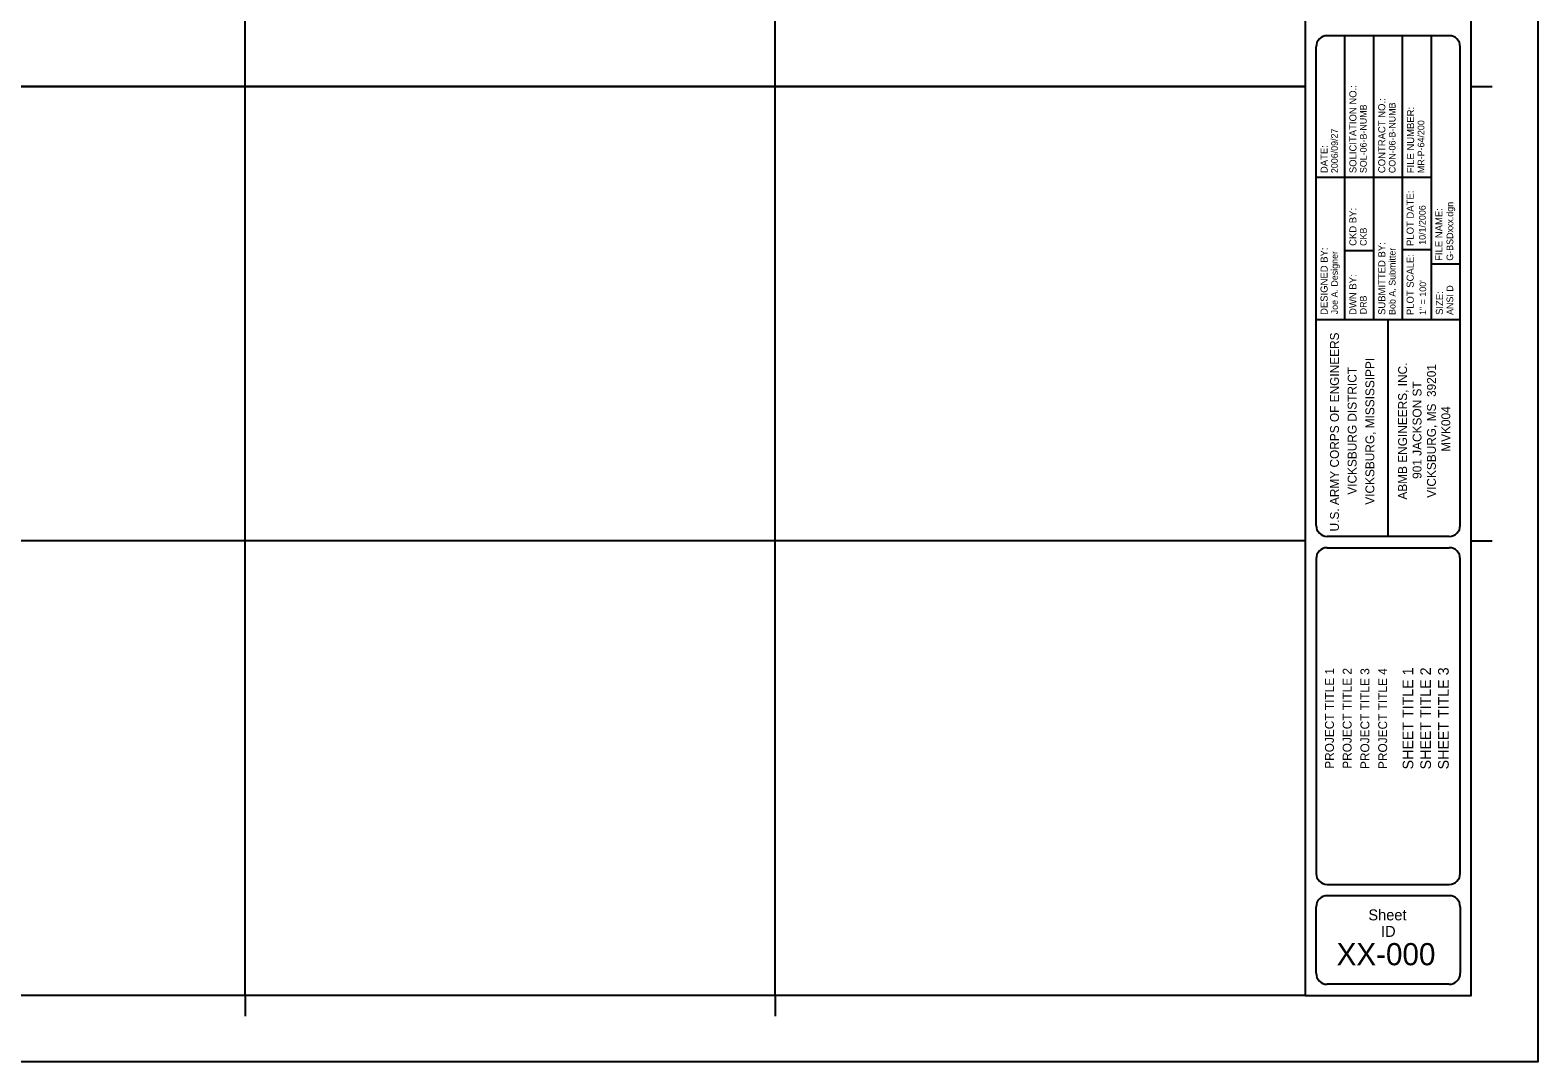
# Model space of a CAD drawing. Extents: x 0 to 2.83, y 0 to 1.83.
# Drawn here: x 1.417 to 2.833, y 0 to 0.97 of the extents above; entities that cross this region are included whole.
import ezdxf

# ---------------------------------------------------------------- set-up
doc = ezdxf.new("R2010")
doc.units = 0
for name, color, linetype in [('G-ANNO-NPLT', 7, 'Continuous'), ('G-ANNO-PRFL', 7, 'Continuous'), ('G-ANNO-TEXT', 7, 'Continuous'), ('G-ANNO-TEXT-SAMP', 7, 'Continuous'), ('G-ANNO-TTLB', 7, 'Continuous'), ('G-ANNO-TTLB-GRID', 7, 'Continuous')]:
    doc.layers.add(name, color=color, linetype=linetype)

msp = doc.modelspace()

# ---------------------------------------------------------------- linework, layer by layer
at = {"layer": 'G-ANNO-NPLT'}
msp.add_line((2.7708, 0.0625), (2.7708, 0.0625), dxfattribs=at)
msp.add_line((2.7708, 0.0625), (2.7708, 0.0625), dxfattribs=at)
msp.add_line((2.7708, 0.0625), (2.7708, 0.0625), dxfattribs=at)
msp.add_line((2.7708, 0.0625), (2.7708, 0.0625), dxfattribs=at)
at = {"layer": 'G-ANNO-PRFL'}
msp.add_line((0.125, 0.9167), (2.6146, 0.9167), dxfattribs=at)
at = {"layer": 'G-ANNO-TEXT'}
for p, q in [((2.7708, 0.9167), (2.7905, 0.9167)), ((2.7708, 0.4896), (2.7905, 0.4896))]:
    msp.add_line(p, q, dxfattribs=at)
at = {"layer": 'G-ANNO-TTLB'}
for p, q in [((2.6521, 0.6979), (2.6521, 0.9646)), ((2.6792, 0.6979), (2.6792, 0.9646)), ((2.7063, 0.6979), (2.7063, 0.9646)), ((2.7333, 0.6979), (2.7333, 0.9646)), ((2.625, 0.5042), (2.625, 0.9542)), ((2.6522, 0.8313), (2.625, 0.8313)), ((2.6793, 0.8313), (2.6521, 0.8313)), ((2.7063, 0.8313), (2.6792, 0.8313)), ((2.7333, 0.8312), (2.7063, 0.8312)), ((2.6521, 0.7628), (2.6793, 0.7628)), ((2.7333, 0.7633), (2.7062, 0.7633)), ((2.7604, 0.7498), (2.7333, 0.7498)), ((2.625, 0.6979), (2.7604, 0.6979)), ((2.6927, 0.4938), (2.6927, 0.6979)), ((1.6188, 0.0625), (1.6188, 0.0428)), ((2.1167, 0.0625), (2.1167, 0.0428))]:
    msp.add_line(p, q, dxfattribs=at)
for points in [[(0, 1.8333), (2.8333, 1.8333), (2.8333, 0), (0, 0)], [(0.125, 1.7708), (2.6146, 1.7708), (2.6146, 0.0625), (0.125, 0.0625)], [(2.6146, 0.0625), (2.7708, 0.0625), (2.7708, 1.7708), (2.6146, 1.7708)]]:
    msp.add_lwpolyline(points, close=True, dxfattribs=at)
for points in [[(2.75, 0.9646), (2.6354, 0.9646)], [(2.7604, 0.5042), (2.7604, 0.9542)], [(2.75, 0.4938), (2.6354, 0.4938)], [(2.6354, 0.4833), (2.75, 0.4833)], [(2.625, 0.4729), (2.625, 0.1771)], [(2.7604, 0.1771), (2.7604, 0.4729)], [(2.6354, 0.1667), (2.75, 0.1667)], [(2.6354, 0.1563), (2.75, 0.1563)], [(2.625, 0.0833), (2.625, 0.1458)], [(2.7604, 0.1458), (2.7604, 0.0833)], [(2.75, 0.0729), (2.6354, 0.0729)]]:
    msp.add_lwpolyline(points, dxfattribs=at)
for centre, start, end in [((2.6354, 0.9542), 90, 180), ((2.75, 0.9542), 0, 90), ((2.6354, 0.5042), 180, 270), ((2.75, 0.5042), 270, 0), ((2.6354, 0.4729), 90, 180), ((2.75, 0.4729), 0, 90), ((2.6354, 0.1771), 180, 270), ((2.75, 0.1771), 270, 0), ((2.6354, 0.1458), 90, 180.0158), ((2.75, 0.1458), 0.0158, 90), ((2.6354, 0.0833), 180.0158, 270), ((2.75, 0.0833), 270, 0.0158)]:
    msp.add_arc(centre, 0.0104, start, end, dxfattribs=at)
at = {"layer": 'G-ANNO-TTLB-GRID'}
for p, q in [((1.6188, 0.0625), (1.6188, 1.7708)), ((2.1167, 0.0625), (2.1167, 1.7708)), ((2.6146, 0.9167), (0.125, 0.9167)), ((2.6146, 0.4896), (0.125, 0.4896))]:
    msp.add_line(p, q, dxfattribs=at)

# ---------------------------------------------------------------- texts
at = {"layer": 'G-ANNO-TEXT'}
for s, height, p in [('SOLICITATION NO.:', 0.006667, (2.6629, 0.8354)), ('CONTRACT NO.:', 0.006667, (2.69, 0.8354)), ('FILE NUMBER:', 0.006667, (2.7171, 0.8353)), ('DATE:', 0.00667, (2.6358, 0.8354)), ('PLOT DATE:', 0.00667, (2.7167, 0.7669)), ('CKD BY:', 0.00667, (2.6629, 0.767)), ('FILE NAME:', 0.00667, (2.7437, 0.7529)), ('SUBMITTED BY:', 0.006667, (2.69, 0.7021)), ('DESIGNED BY:', 0.006667, (2.6358, 0.7021)), ('PLOT SCALE:', 0.006667, (2.7167, 0.7019)), ('DWN BY:', 0.00667, (2.6629, 0.7021)), ('SIZE:', 0.00667, (2.7442, 0.7021))]:
    msp.add_text(s, height=height, rotation=90, dxfattribs=at).set_placement(p)
for s, p in [('Sheet', (2.6741, 0.133)), ('ID', (2.686, 0.1175))]:
    msp.add_text(s, height=0.01025, dxfattribs=at).set_placement(p)
at = {"layer": 'G-ANNO-TEXT-SAMP'}
for s, height, p in [('SOL-06-B-NUMB', 0.00625, (2.6725, 0.8354)), ('CON-06-B-NUMB', 0.00625, (2.6996, 0.8354)), ('MR-P-64/200', 0.00625, (2.7267, 0.8354)), ('2006/09/27', 0.00625, (2.6454, 0.8354)), ('G-BSDxxx.dgn', 0.00625, (2.7538, 0.7531)), ('10/1/2006', 0.00625, (2.7279, 0.768)), ('CKB', 0.00625, (2.6725, 0.767)), ('Bob A. Submitter', 0.00625, (2.6996, 0.7021)), ('Joe A. Designer', 0.00625, (2.6454, 0.7027)), ('1" = 100\'', 0.00625, (2.7284, 0.7021)), ('ANSI D', 0.00625, (2.7538, 0.7021)), ('DRB', 0.00625, (2.6725, 0.7027)), ('U.S. ARMY CORPS OF ENGINEERS', 0.008333, (2.6464, 0.4986)), ('VICKSBURG DISTRICT', 0.008333, (2.663, 0.5331)), ('VICKSBURG, MISSISSIPPI', 0.008333, (2.6797, 0.5237)), ('ABMB ENGINEERS, INC.', 0.008333, (2.7104, 0.5285)), ('VICKSBURG, MS  39201', 0.008333, (2.7375, 0.5302)), ('901 JACKSON ST', 0.008333, (2.724, 0.548)), ('MVK004', 0.00833, (2.751, 0.5735)), ('PROJECT TITLE 1', 0.008333, (2.6417, 0.2755)), ('PROJECT TITLE 2', 0.008333, (2.6583, 0.2755)), ('PROJECT TITLE 3', 0.008333, (2.675, 0.2753)), ('PROJECT TITLE 4', 0.008333, (2.6917, 0.2753)), ('SHEET TITLE 1', 0.01, (2.7163, 0.2749)), ('SHEET TITLE 2', 0.01, (2.7329, 0.2749)), ('SHEET TITLE 3', 0.01, (2.7496, 0.2749))]:
    msp.add_text(s, height=height, rotation=90, dxfattribs=at).set_placement(p)
msp.add_text('XX-000', height=0.02083, dxfattribs=at).set_placement((2.6442, 0.0908))

doc.saveas('drawing.dxf')
